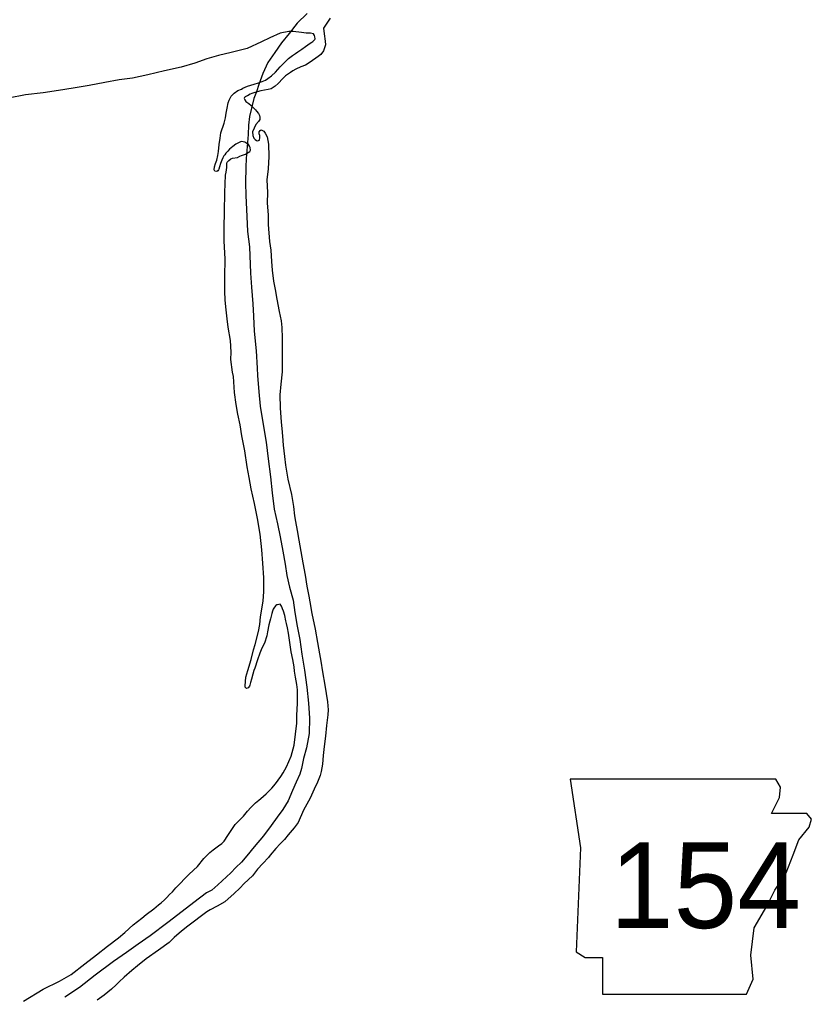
# Model space of a CAD drawing. Extents: x -83719 to 153526, y -11835 to 11446.
# Drawn here: x -1487.2 to -1291.8, y 240.1 to 481.1 of the extents above; entities that cross this region are included whole.
import ezdxf

# ---------------------------------------------------------------- set-up
doc = ezdxf.new("R2010")
doc.units = 0
for name, color, linetype in [('Level 2', 7, 'Continuous'), ('Level 21', 7, 'Continuous'), ('Level 9', 7, 'Continuous')]:
    doc.layers.add(name, color=color, linetype=linetype)

msp = doc.modelspace()

# ---------------------------------------------------------------- linework, layer by layer
at = {"layer": 'Level 2'}
for points in [[(-1416.24, 482.6), (-1418.7, 480.2), (-1420.7, 477.7), (-1422.54, 475.41), (-1424.24, 472.99), (-1425.94, 470.53), (-1427.17, 467.81), (-1428.14, 465.1), (-1428.78, 463.28), (-1429.43, 461.64), (-1429.97, 459.26), (-1430.44, 457.19), (-1430.68, 455.05), (-1430.82, 452.74), (-1431.28, 446.86), (-1431.39, 444.69), (-1431.44, 440.85), (-1431.4, 437.71), (-1431.14, 432.5), (-1430.96, 428.83), (-1430.44, 425.06), (-1430.26, 418.52), (-1429.99, 415.12), (-1429.64, 410.95), (-1429.5, 407.91), (-1429.29, 404.27), (-1428.83, 399.4), (-1428.54, 395.07), (-1428.46, 393.3), (-1428.17, 389.29), (-1427.83, 385.76), (-1427.18, 381.69), (-1426.39, 376.83), (-1425.87, 372.76), (-1425.32, 368.32), (-1424.9, 364.39), (-1424.35, 360.32), (-1423.58, 356.72), (-1422.94, 353.53), (-1422.23, 349.99), (-1421.69, 346.79), (-1421.29, 343.93), (-1420.59, 341.06), (-1419.72, 337.87), (-1419.28, 334.83), (-1418.67, 331.44), (-1418.03, 328.17), (-1417.55, 324.57), (-1416.9, 320.57), (-1416.32, 316.37), (-1415.91, 312.47), (-1415.69, 308.76), (-1415.75, 304.96), (-1416.44, 301.41), (-1417.14, 298.83), (-1417.67, 296.35), (-1418.09, 294.91), (-1418.96, 292.93), (-1419.87, 290.88), (-1420.97, 288.37), (-1422.24, 286.25), (-1423.62, 284.36)], [(-1416.24, 482.6), (-1418.7, 480.2), (-1420.7, 477.7), (-1422.54, 475.41), (-1424.24, 472.99), (-1425.94, 470.53), (-1427.17, 467.81), (-1428.14, 465.1), (-1428.78, 463.28), (-1429.43, 461.64), (-1429.97, 459.26), (-1430.44, 457.19), (-1430.68, 455.05), (-1430.82, 452.74), (-1431.28, 446.86), (-1431.39, 444.69), (-1431.44, 440.85), (-1431.4, 437.71), (-1431.14, 432.5), (-1430.96, 428.83), (-1430.44, 425.06), (-1430.26, 418.52), (-1429.99, 415.12), (-1429.64, 410.95), (-1429.5, 407.91), (-1429.29, 404.27), (-1428.83, 399.4), (-1428.54, 395.07), (-1428.46, 393.3), (-1428.17, 389.29), (-1427.83, 385.76), (-1427.18, 381.69), (-1426.39, 376.83), (-1425.87, 372.76), (-1425.32, 368.32), (-1424.9, 364.39), (-1424.35, 360.32), (-1423.58, 356.72), (-1422.94, 353.53), (-1422.23, 349.99), (-1421.69, 346.79), (-1421.29, 343.93), (-1420.59, 341.06), (-1419.72, 337.87), (-1419.28, 334.83), (-1418.67, 331.44), (-1418.03, 328.17), (-1417.55, 324.57), (-1416.9, 320.57), (-1416.32, 316.37), (-1415.91, 312.47), (-1415.69, 308.76), (-1415.75, 304.96), (-1416.44, 301.41), (-1417.14, 298.83), (-1417.67, 296.35), (-1418.09, 294.91), (-1418.96, 292.93), (-1419.87, 290.88), (-1420.97, 288.37), (-1422.24, 286.25), (-1423.62, 284.36)], [(-1423.62, 284.36), (-1425.09, 282.27), (-1426.99, 279.75), (-1429.32, 277.05), (-1431.09, 274.79), (-1432.47, 273.24), (-1433.85, 271.89), (-1435.04, 270.64), (-1438.3, 267.66)], [(-1423.62, 284.36), (-1425.09, 282.27), (-1426.99, 279.75), (-1429.32, 277.05), (-1431.09, 274.79), (-1432.47, 273.24), (-1433.85, 271.89), (-1435.04, 270.64), (-1438.3, 267.66)], [(-1438.3, 267.66), (-1439.73, 266.33), (-1441.05, 265.64), (-1444.17, 263.31), (-1447.1, 261.03), (-1450.59, 258.33), (-1454.96, 255.09), (-1457.92, 252.97), (-1460.82, 250.95), (-1464.05, 248.76), (-1468.52, 245.35), (-1472.43, 242.31), (-1476.02, 239.92)], [(-1438.3, 267.66), (-1439.73, 266.33), (-1441.05, 265.64), (-1444.17, 263.31), (-1447.1, 261.03), (-1450.59, 258.33), (-1454.96, 255.09), (-1457.92, 252.97), (-1460.82, 250.95), (-1464.05, 248.76), (-1468.52, 245.35), (-1472.43, 242.31), (-1476.02, 239.92)]]:
    msp.add_lwpolyline(points, dxfattribs=at)
at = {"layer": 'Level 21'}
msp.add_lwpolyline([(-1351.31, 293.69), (-1348.77, 276.78), (-1349.9, 251.12), (-1347.64, 249.71), (-1343.41, 249.71), (-1343.41, 240.68), (-1307.88, 240.68), (-1306.19, 244.35), (-1306.76, 250.27), (-1305.91, 257.04), (-1302.81, 262.4), (-1300.84, 266.34), (-1298.02, 270.57), (-1296.32, 275.08), (-1294.91, 278.75), (-1292.38, 281.85), (-1291.81, 283.82), (-1292.94, 285.23), (-1301.68, 285.23), (-1299.71, 289.18), (-1299.43, 291.72), (-1300.6, 293.67)], close=True, dxfattribs=at)
at = {"layer": 'Level 9'}
for points in [[(-1410.59, 481.46), (-1412.2, 479), (-1412.08, 477.6), (-1411.76, 475.8)], [(-1410.59, 481.46), (-1412.2, 479), (-1412.08, 477.6), (-1411.76, 475.8)], [(-1415.74, 475.16), (-1415.12, 475.56), (-1414.82, 475.74), (-1414.59, 475.97), (-1414.39, 476.17), (-1414.29, 476.38), (-1414.33, 476.84), (-1414.47, 477.18), (-1414.64, 477.57), (-1415.41, 477.8), (-1416.51, 477.75), (-1417.61, 477.91), (-1419.71, 478.18), (-1420.74, 478.17), (-1422.9, 477.78), (-1425.42, 476.58), (-1427.5, 475.62), (-1431.08, 474.01), (-1434.96, 473.03), (-1438.12, 472.29), (-1441, 471.46), (-1443.99, 470.35), (-1447.34, 469.41), (-1451.42, 468.5), (-1455.57, 467.45), (-1459.36, 466.64), (-1462.62, 466.23), (-1466.2, 465.56), (-1470.02, 464.81), (-1473.98, 464.23), (-1477.57, 463.65), (-1481.39, 463.04), (-1485.78, 462.52), (-1489.93, 461.74)], [(-1415.74, 475.16), (-1415.12, 475.56), (-1414.82, 475.74), (-1414.59, 475.97), (-1414.39, 476.17), (-1414.29, 476.38), (-1414.33, 476.84), (-1414.47, 477.18), (-1414.64, 477.57), (-1415.41, 477.8), (-1416.51, 477.75), (-1417.61, 477.91), (-1419.71, 478.18), (-1420.74, 478.17), (-1422.9, 477.78), (-1425.42, 476.58), (-1427.5, 475.62), (-1431.08, 474.01), (-1434.96, 473.03), (-1438.12, 472.29), (-1441, 471.46), (-1443.99, 470.35), (-1447.34, 469.41), (-1451.42, 468.5), (-1455.57, 467.45), (-1459.36, 466.64), (-1462.62, 466.23), (-1466.2, 465.56), (-1470.02, 464.81), (-1473.98, 464.23), (-1477.57, 463.65), (-1481.39, 463.04), (-1485.78, 462.52), (-1489.93, 461.74)], [(-1432.77, 381.09), (-1433.33, 383.72), (-1433.79, 386.12), (-1434.16, 389.12), (-1434.41, 393.03), (-1434.63, 394.09), (-1435.06, 397.23), (-1435.02, 399.07), (-1435.19, 401.97), (-1435.76, 405.2), (-1435.99, 407.3), (-1436.25, 409.5), (-1436.48, 411.87), (-1436.54, 414.11), (-1436.55, 417.65), (-1436.47, 422.06), (-1436.69, 426.43), (-1436.7, 429.8), (-1436.61, 433.68), (-1436.54, 438.42), (-1436.39, 442.73), (-1436.23, 443.5), (-1436.14, 444.07), (-1436.08, 444.6), (-1436.08, 445.07), (-1436.06, 445.57), (-1435.96, 445.94), (-1435.6, 446.31), (-1435.04, 446.72), (-1434.64, 446.92), (-1433.45, 447.07), (-1432.88, 447.38), (-1432.42, 447.61), (-1431.49, 447.93), (-1431.23, 448.06), (-1430.37, 448.54), (-1430.37, 448.57), (-1430.24, 448.88), (-1430.31, 449.54), (-1430.45, 449.88), (-1430.72, 450.27), (-1431.12, 450.5), (-1431.59, 450.83), (-1432.03, 450.99), (-1432.53, 451.05), (-1432.99, 450.81), (-1433.85, 450.34), (-1434.58, 449.76), (-1435.37, 449.12), (-1435.8, 448.68), (-1436.29, 448.14), (-1436.55, 447.77), (-1436.81, 447.46), (-1437.07, 447.03), (-1437.27, 446.42), (-1437.59, 445.58), (-1437.85, 444.75), (-1438.01, 444.21), (-1438.14, 444.01), (-1438.3, 443.81), (-1438.57, 443.67), (-1439, 443.73), (-1439.2, 444.06), (-1439.11, 444.8), (-1438.86, 445.64), (-1438.57, 446.44), (-1438.25, 447.58), (-1438.13, 448.55), (-1437.98, 450.29), (-1437.7, 451.86), (-1437.58, 453.13), (-1436.75, 455.58), (-1436.43, 456.85), (-1436.21, 458.02), (-1435.99, 459.29), (-1435.74, 460.57), (-1435.48, 461.24), (-1434.96, 462.21), (-1434.27, 462.99), (-1433.35, 463.63), (-1432.42, 463.94), (-1432.12, 464.15), (-1430.97, 464.7), (-1429.34, 465.15), (-1428.21, 465.5), (-1427.32, 465.81), (-1426.56, 466.18), (-1425.93, 466.56), (-1425.07, 467.23), (-1424.08, 468.15), (-1423.49, 468.76), (-1422.9, 469.43), (-1421.95, 470.44), (-1420.86, 471.49), (-1419.87, 472.27), (-1419.08, 472.78), (-1418.52, 473.12), (-1417.56, 473.83), (-1416.63, 474.48), (-1416.07, 474.89), (-1415.74, 475.16)], [(-1432.77, 381.09), (-1433.33, 383.72), (-1433.79, 386.12), (-1434.16, 389.12), (-1434.41, 393.03), (-1434.63, 394.09), (-1435.06, 397.23), (-1435.02, 399.07), (-1435.19, 401.97), (-1435.76, 405.2), (-1435.99, 407.3), (-1436.25, 409.5), (-1436.48, 411.87), (-1436.54, 414.11), (-1436.55, 417.65), (-1436.47, 422.06), (-1436.69, 426.43), (-1436.7, 429.8), (-1436.61, 433.68), (-1436.54, 438.42), (-1436.39, 442.73), (-1436.23, 443.5), (-1436.14, 444.07), (-1436.08, 444.6), (-1436.08, 445.07), (-1436.06, 445.57), (-1435.96, 445.94), (-1435.6, 446.31), (-1435.04, 446.72), (-1434.64, 446.92), (-1433.45, 447.07), (-1432.88, 447.38), (-1432.42, 447.61), (-1431.49, 447.93), (-1431.23, 448.06), (-1430.37, 448.54), (-1430.37, 448.57), (-1430.24, 448.88), (-1430.31, 449.54), (-1430.45, 449.88), (-1430.72, 450.27), (-1431.12, 450.5), (-1431.59, 450.83), (-1432.03, 450.99), (-1432.53, 451.05), (-1432.99, 450.81), (-1433.85, 450.34), (-1434.58, 449.76), (-1435.37, 449.12), (-1435.8, 448.68), (-1436.29, 448.14), (-1436.55, 447.77), (-1436.81, 447.46), (-1437.07, 447.03), (-1437.27, 446.42), (-1437.59, 445.58), (-1437.85, 444.75), (-1438.01, 444.21), (-1438.14, 444.01), (-1438.3, 443.81), (-1438.57, 443.67), (-1439, 443.73), (-1439.2, 444.06), (-1439.11, 444.8), (-1438.86, 445.64), (-1438.57, 446.44), (-1438.25, 447.58), (-1438.13, 448.55), (-1437.98, 450.29), (-1437.7, 451.86), (-1437.58, 453.13), (-1436.75, 455.58), (-1436.43, 456.85), (-1436.21, 458.02), (-1435.99, 459.29), (-1435.74, 460.57), (-1435.48, 461.24), (-1434.96, 462.21), (-1434.27, 462.99), (-1433.35, 463.63), (-1432.42, 463.94), (-1432.12, 464.15), (-1430.97, 464.7), (-1429.34, 465.15), (-1428.21, 465.5), (-1427.32, 465.81), (-1426.56, 466.18), (-1425.93, 466.56), (-1425.07, 467.23), (-1424.08, 468.15), (-1423.49, 468.76), (-1422.9, 469.43), (-1421.95, 470.44), (-1420.86, 471.49), (-1419.87, 472.27), (-1419.08, 472.78), (-1418.52, 473.12), (-1417.56, 473.83), (-1416.63, 474.48), (-1416.07, 474.89), (-1415.74, 475.16)], [(-1411.76, 475.8), (-1411.71, 474.9), (-1412.23, 473.43), (-1412.91, 472.52), (-1413.51, 472.01), (-1415.49, 470.62), (-1416.64, 469.87), (-1417.77, 469.46), (-1419.06, 468.87), (-1419.76, 468.47), (-1420.39, 468.06), (-1421.57, 467.24), (-1422.23, 466.6), (-1423.42, 465.35), (-1424.14, 464.67), (-1425.13, 464.03), (-1425.86, 463.85), (-1427.65, 463.5), (-1429.15, 463.08), (-1429.91, 462.84), (-1430.31, 462.73), (-1430.97, 462.32), (-1431.24, 462.25), (-1431.57, 462.08), (-1431.7, 461.88), (-1431.79, 461.61), (-1431.66, 461.28), (-1431.35, 460.88), (-1430.65, 460.39), (-1430.04, 459.9), (-1429.64, 459.47), (-1429.26, 459.07), (-1428.96, 458.81), (-1428.72, 458.48), (-1428.29, 457.98), (-1428.18, 457.78), (-1428.01, 457.42), (-1427.91, 457.05), (-1427.9, 456.48), (-1428.29, 455.98), (-1428.92, 455.2), (-1429.76, 453.42), (-1429.68, 452.52), (-1429.38, 451.82), (-1429.04, 451.49), (-1428.74, 451.26), (-1428.5, 451.2), (-1428.04, 451.37), (-1427.88, 452.04), (-1427.95, 452.54), (-1428.06, 452.94), (-1428.1, 453.44), (-1427.8, 453.78), (-1427.57, 453.95), (-1426.93, 453.59), (-1426.63, 453.09), (-1426.08, 452.16), (-1425.76, 450.4), (-1425.69, 447.36), (-1425.89, 444.25), (-1426.19, 441.54), (-1426.05, 438.47), (-1426.12, 435.93), (-1425.88, 432.83), (-1425.85, 430.59), (-1425.5, 426.39), (-1425.21, 424.26), (-1425.04, 421.39), (-1424.88, 419.25), (-1424.51, 416.55), (-1424.12, 414.52), (-1423.69, 412.12), (-1423.16, 409.09), (-1422.69, 406.79), (-1422.47, 405.12), (-1422.41, 402.48), (-1422.41, 399.75), (-1422.38, 397.24), (-1422.44, 394.24), (-1422.7, 391.16), (-1422.97, 388.55), (-1422.9, 385.35), (-1422.62, 381.75), (-1422.47, 380.24), (-1422.34, 378.34), (-1422.15, 376.11), (-1421.85, 373.34), (-1421.59, 371.17), (-1421.37, 369.67), (-1420.98, 367.71), (-1420.07, 363.98), (-1419.63, 360.98), (-1419.34, 358.64), (-1419.12, 357.31), (-1418.73, 355.04), (-1418.33, 352.71), (-1417.8, 349.91), (-1417.3, 347.11), (-1416.73, 344.05), (-1416.36, 341.31), (-1415.83, 338.88)], [(-1411.76, 475.8), (-1411.71, 474.9), (-1412.23, 473.43), (-1412.91, 472.52), (-1413.51, 472.01), (-1415.49, 470.62), (-1416.64, 469.87), (-1417.77, 469.46), (-1419.06, 468.87), (-1419.76, 468.47), (-1420.39, 468.06), (-1421.57, 467.24), (-1422.23, 466.6), (-1423.42, 465.35), (-1424.14, 464.67), (-1425.13, 464.03), (-1425.86, 463.85), (-1427.65, 463.5), (-1429.15, 463.08), (-1429.91, 462.84), (-1430.31, 462.73), (-1430.97, 462.32), (-1431.24, 462.25), (-1431.57, 462.08), (-1431.7, 461.88), (-1431.79, 461.61), (-1431.66, 461.28), (-1431.35, 460.88), (-1430.65, 460.39), (-1430.04, 459.9), (-1429.64, 459.47), (-1429.26, 459.07), (-1428.96, 458.81), (-1428.72, 458.48), (-1428.29, 457.98), (-1428.18, 457.78), (-1428.01, 457.42), (-1427.91, 457.05), (-1427.9, 456.48), (-1428.29, 455.98), (-1428.92, 455.2), (-1429.76, 453.42), (-1429.68, 452.52), (-1429.38, 451.82), (-1429.04, 451.49), (-1428.74, 451.26), (-1428.5, 451.2), (-1428.04, 451.37), (-1427.88, 452.04), (-1427.95, 452.54), (-1428.06, 452.94), (-1428.1, 453.44), (-1427.8, 453.78), (-1427.57, 453.95), (-1426.93, 453.59), (-1426.63, 453.09), (-1426.08, 452.16), (-1425.76, 450.4), (-1425.69, 447.36), (-1425.89, 444.25), (-1426.19, 441.54), (-1426.05, 438.47), (-1426.12, 435.93), (-1425.88, 432.83), (-1425.85, 430.59), (-1425.5, 426.39), (-1425.21, 424.26), (-1425.04, 421.39), (-1424.88, 419.25), (-1424.51, 416.55), (-1424.12, 414.52), (-1423.69, 412.12), (-1423.16, 409.09), (-1422.69, 406.79), (-1422.47, 405.12), (-1422.41, 402.48), (-1422.41, 399.75), (-1422.38, 397.24), (-1422.44, 394.24), (-1422.7, 391.16), (-1422.97, 388.55), (-1422.9, 385.35), (-1422.62, 381.75), (-1422.47, 380.24), (-1422.34, 378.34), (-1422.15, 376.11), (-1421.85, 373.34), (-1421.59, 371.17), (-1421.37, 369.67), (-1420.98, 367.71), (-1420.07, 363.98), (-1419.63, 360.98), (-1419.34, 358.64), (-1419.12, 357.31), (-1418.73, 355.04), (-1418.33, 352.71), (-1417.8, 349.91), (-1417.3, 347.11), (-1416.73, 344.05), (-1416.36, 341.31), (-1415.83, 338.88)], [(-1448.68, 266.87), (-1445.32, 270.29), (-1443.28, 272.15), (-1441.77, 274.13), (-1440.26, 275.59), (-1439.4, 276.3), (-1438.11, 277.25), (-1437.32, 277.82), (-1436.76, 278.43), (-1435.82, 279.78), (-1435.29, 280.59), (-1433.98, 282.5), (-1432.9, 283.62), (-1431.98, 284.57), (-1430.96, 285.78), (-1430.14, 286.69), (-1429.02, 287.84), (-1428.2, 288.55), (-1427.67, 288.96), (-1426.35, 290.07), (-1425, 291.46), (-1424.05, 292.54), (-1422.71, 294.39), (-1422.15, 295.3), (-1421.37, 296.78), (-1420.21, 299.36), (-1419.41, 302.11), (-1419.11, 304.85), (-1418.81, 307.49), (-1418.77, 309.4), (-1418.64, 312.47), (-1418.63, 314.67), (-1418.64, 315.74), (-1418.83, 317.04), (-1419.12, 318.87), (-1419.37, 320.37), (-1419.48, 321.44), (-1419.8, 323.24), (-1420.22, 325.14), (-1420.63, 327.97), (-1420.88, 329.71), (-1421.1, 331.04), (-1421.34, 332.11), (-1421.48, 332.81), (-1421.73, 334.1), (-1422.08, 335.14), (-1422.32, 335.77), (-1422.52, 336.2), (-1422.59, 336.43), (-1422.9, 336.9), (-1423.26, 336.79), (-1423.53, 336.76), (-1423.73, 336.75), (-1423.99, 336.52), (-1424.29, 336.11), (-1424.65, 335.61), (-1424.81, 335.17), (-1424.97, 334.57), (-1425.32, 333.26), (-1425.45, 332.73), (-1425.7, 331.75), (-1426.05, 330.08), (-1426.2, 329.08), (-1426.81, 327.3), (-1427.43, 325.99), (-1427.91, 324.78), (-1428.52, 323.11), (-1429.16, 321.06), (-1429.36, 320.53), (-1429.68, 319.65), (-1429.96, 318.41), (-1430.25, 317.58), (-1430.41, 316.94), (-1430.51, 316.64), (-1430.77, 316.24), (-1431.17, 316.1), (-1431.54, 316.39), (-1431.58, 316.76), (-1431.34, 318.87), (-1430.86, 320.51), (-1430.09, 323.22), (-1429.49, 325.6), (-1429.07, 326.97), (-1428.28, 330.12), (-1427.93, 331.86), (-1427.76, 333.8), (-1427.32, 336.11), (-1427.11, 337.72), (-1426.97, 339.92), (-1426.91, 343.36), (-1427.19, 346.96), (-1427.39, 350.27), (-1427.84, 354.17), (-1428.52, 358), (-1429.27, 361.73), (-1430.04, 365.36), (-1430.58, 368.1), (-1431.01, 370.73), (-1431.66, 374.69), (-1432.33, 378.39), (-1432.77, 381.09)], [(-1448.68, 266.87), (-1445.32, 270.29), (-1443.28, 272.15), (-1441.77, 274.13), (-1440.26, 275.59), (-1439.4, 276.3), (-1438.11, 277.25), (-1437.32, 277.82), (-1436.76, 278.43), (-1435.82, 279.78), (-1435.29, 280.59), (-1433.98, 282.5), (-1432.9, 283.62), (-1431.98, 284.57), (-1430.96, 285.78), (-1430.14, 286.69), (-1429.02, 287.84), (-1428.2, 288.55), (-1427.67, 288.96), (-1426.35, 290.07), (-1425, 291.46), (-1424.05, 292.54), (-1422.71, 294.39), (-1422.15, 295.3), (-1421.37, 296.78), (-1420.21, 299.36), (-1419.41, 302.11), (-1419.11, 304.85), (-1418.81, 307.49), (-1418.77, 309.4), (-1418.64, 312.47), (-1418.63, 314.67), (-1418.64, 315.74), (-1418.83, 317.04), (-1419.12, 318.87), (-1419.37, 320.37), (-1419.48, 321.44), (-1419.8, 323.24), (-1420.22, 325.14), (-1420.63, 327.97), (-1420.88, 329.71), (-1421.1, 331.04), (-1421.34, 332.11), (-1421.48, 332.81), (-1421.73, 334.1), (-1422.08, 335.14), (-1422.32, 335.77), (-1422.52, 336.2), (-1422.59, 336.43), (-1422.9, 336.9), (-1423.26, 336.79), (-1423.53, 336.76), (-1423.73, 336.75), (-1423.99, 336.52), (-1424.29, 336.11), (-1424.65, 335.61), (-1424.81, 335.17), (-1424.97, 334.57), (-1425.32, 333.26), (-1425.45, 332.73), (-1425.7, 331.75), (-1426.05, 330.08), (-1426.2, 329.08), (-1426.81, 327.3), (-1427.43, 325.99), (-1427.91, 324.78), (-1428.52, 323.11), (-1429.16, 321.06), (-1429.36, 320.53), (-1429.68, 319.65), (-1429.96, 318.41), (-1430.25, 317.58), (-1430.41, 316.94), (-1430.51, 316.64), (-1430.77, 316.24), (-1431.17, 316.1), (-1431.54, 316.39), (-1431.58, 316.76), (-1431.34, 318.87), (-1430.86, 320.51), (-1430.09, 323.22), (-1429.49, 325.6), (-1429.07, 326.97), (-1428.28, 330.12), (-1427.93, 331.86), (-1427.76, 333.8), (-1427.32, 336.11), (-1427.11, 337.72), (-1426.97, 339.92), (-1426.91, 343.36), (-1427.19, 346.96), (-1427.39, 350.27), (-1427.84, 354.17), (-1428.52, 358), (-1429.27, 361.73), (-1430.04, 365.36), (-1430.58, 368.1), (-1431.01, 370.73), (-1431.66, 374.69), (-1432.33, 378.39), (-1432.77, 381.09)], [(-1415.83, 338.88), (-1415.55, 337.45), (-1415.05, 334.55), (-1414.3, 330.68), (-1413.66, 327.39), (-1413.19, 324.62), (-1412.87, 322.79), (-1412.44, 320.15), (-1411.86, 316.86), (-1411.22, 312.82), (-1411.02, 310.79), (-1411.11, 309.55), (-1411.44, 306.94), (-1411.71, 304.33), (-1412.08, 301.79), (-1412.28, 299.52), (-1412.46, 297.45), (-1412.77, 295.61), (-1413.02, 294.6), (-1413.67, 292.99), (-1414.48, 291.21), (-1415.48, 289.03), (-1416.36, 287.52), (-1417.11, 286.07), (-1418.47, 282.99), (-1419.46, 281.74), (-1420.97, 279.95), (-1421.85, 278.84), (-1422.94, 277.76), (-1423.99, 276.61), (-1425.37, 274.92), (-1425.76, 274.39), (-1427.17, 272.87), (-1428.49, 271.52), (-1429.77, 269.9), (-1431.81, 267.94), (-1432.83, 266.79)], [(-1415.83, 338.88), (-1415.55, 337.45), (-1415.05, 334.55), (-1414.3, 330.68), (-1413.66, 327.39), (-1413.19, 324.62), (-1412.87, 322.79), (-1412.44, 320.15), (-1411.86, 316.86), (-1411.22, 312.82), (-1411.02, 310.79), (-1411.11, 309.55), (-1411.44, 306.94), (-1411.71, 304.33), (-1412.08, 301.79), (-1412.28, 299.52), (-1412.46, 297.45), (-1412.77, 295.61), (-1413.02, 294.6), (-1413.67, 292.99), (-1414.48, 291.21), (-1415.48, 289.03), (-1416.36, 287.52), (-1417.11, 286.07), (-1418.47, 282.99), (-1419.46, 281.74), (-1420.97, 279.95), (-1421.85, 278.84), (-1422.94, 277.76), (-1423.99, 276.61), (-1425.37, 274.92), (-1425.76, 274.39), (-1427.17, 272.87), (-1428.49, 271.52), (-1429.77, 269.9), (-1431.81, 267.94), (-1432.83, 266.79)], [(-1486.23, 238.91), (-1481.35, 241.93), (-1477.35, 243.87), (-1474.51, 245.48), (-1471.06, 248.15), (-1468.2, 250.36), (-1465.54, 252.51), (-1462.78, 254.56), (-1461.27, 255.92), (-1459.17, 257.73), (-1457.06, 259.4), (-1455.95, 260.35), (-1454.1, 261.68), (-1452.89, 262.7), (-1452.3, 263.18), (-1451.48, 263.9), (-1450.85, 264.51), (-1450.17, 265.22), (-1449.45, 265.93), (-1448.68, 266.87)], [(-1486.23, 238.91), (-1481.35, 241.93), (-1477.35, 243.87), (-1474.51, 245.48), (-1471.06, 248.15), (-1468.2, 250.36), (-1465.54, 252.51), (-1462.78, 254.56), (-1461.27, 255.92), (-1459.17, 257.73), (-1457.06, 259.4), (-1455.95, 260.35), (-1454.1, 261.68), (-1452.89, 262.7), (-1452.3, 263.18), (-1451.48, 263.9), (-1450.85, 264.51), (-1450.17, 265.22), (-1449.45, 265.93), (-1448.68, 266.87)], [(-1432.83, 266.79), (-1434.25, 265.51), (-1436.58, 263.47), (-1438.46, 262.41), (-1440.15, 261.48), (-1441.01, 261), (-1442.62, 259.73), (-1444.03, 258.71), (-1445.68, 257.45), (-1447.25, 256.22), (-1449.03, 254.62), (-1450.3, 253.43), (-1452.94, 251.55), (-1456, 249.39), (-1458.1, 247.69), (-1459.51, 246.5), (-1461.38, 244.86), (-1462.63, 243.71), (-1463.38, 242.96), (-1464.56, 241.87), (-1466.37, 240.41), (-1468.05, 239.18)], [(-1432.83, 266.79), (-1434.25, 265.51), (-1436.58, 263.47), (-1438.46, 262.41), (-1440.15, 261.48), (-1441.01, 261), (-1442.62, 259.73), (-1444.03, 258.71), (-1445.68, 257.45), (-1447.25, 256.22), (-1449.03, 254.62), (-1450.3, 253.43), (-1452.94, 251.55), (-1456, 249.39), (-1458.1, 247.69), (-1459.51, 246.5), (-1461.38, 244.86), (-1462.63, 243.71), (-1463.38, 242.96), (-1464.56, 241.87), (-1466.37, 240.41), (-1468.05, 239.18)]]:
    msp.add_lwpolyline(points, dxfattribs=at)

# ---------------------------------------------------------------- texts
at = {"layer": 'Level 21'}
msp.add_text('154', height=21.12, dxfattribs=at).set_placement((-1341.54, 256.98))

doc.saveas('drawing.dxf')
